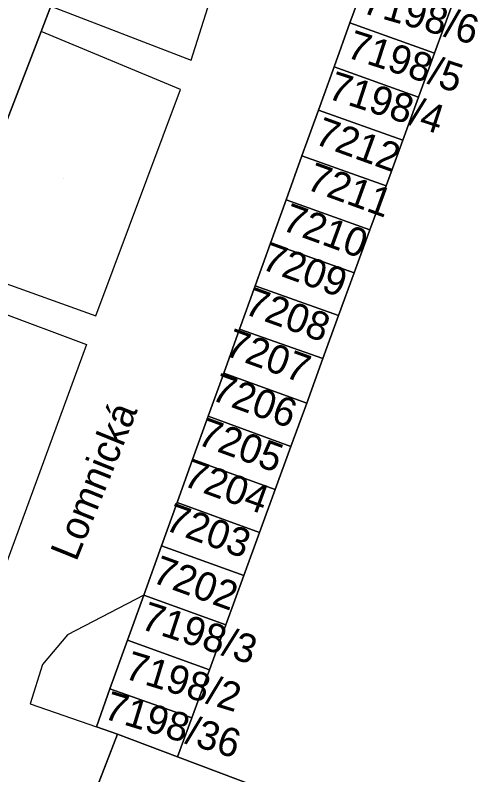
# Model space of a CAD drawing. Extents: x -266199 to -261993, y -1239047 to -1235108.
# Drawn here: x -263606.2 to -263574, y -1236545.7 to -1236492.8 of the extents above; entities that cross this region are included whole.
import ezdxf

# ---------------------------------------------------------------- set-up
doc = ezdxf.new("R2010")
doc.units = 0
for name, color, linetype in [('body_kn', 7, 'Continuous'), ('kladpar_druhypozemkov', 7, 'Continuous'), ('kladpar_hranice', 7, 'Continuous'), ('kladpar_parcelnecisla', 7, 'Continuous'), ('kladpar_plochy', 7, 'Continuous'), ('popisy', 7, 'Continuous'), ('zappar_hrandruhpozemk', 7, 'Continuous')]:
    doc.layers.add(name, color=color, linetype=linetype)

msp = doc.modelspace()

# ---------------------------------------------------------------- linework, layer by layer
at = {"layer": 'body_kn'}
for p, q in [((-263582.87, -1236493.34), (-263582.87, -1236493.34)), ((-263582.87, -1236493.34), (-263582.87, -1236493.34)), ((-263604.37, -1236493.93), (-263604.37, -1236493.93)), ((-263576.98, -1236495.45), (-263576.98, -1236495.45)), ((-263593.93, -1236495.93), (-263593.93, -1236495.93)), ((-263583.97, -1236496.4), (-263583.97, -1236496.4)), ((-263583.97, -1236496.4), (-263583.97, -1236496.4)), ((-263594.67, -1236497.98), (-263594.67, -1236497.98)), ((-263578.1, -1236498.51), (-263578.1, -1236498.51)), ((-263585.05, -1236499.41), (-263585.05, -1236499.41)), ((-263585.05, -1236499.41), (-263585.05, -1236499.41)), ((-263579.19, -1236501.51), (-263579.19, -1236501.51)), ((-263586.21, -1236502.61), (-263586.21, -1236502.61)), ((-263586.21, -1236502.61), (-263586.21, -1236502.61)), ((-263580.35, -1236504.7), (-263580.35, -1236504.7)), ((-263587.31, -1236505.67), (-263587.31, -1236505.67)), ((-263587.31, -1236505.67), (-263587.31, -1236505.67)), ((-263581.47, -1236507.75), (-263581.47, -1236507.75)), ((-263588.39, -1236508.68), (-263588.39, -1236508.68)), ((-263588.39, -1236508.68), (-263588.39, -1236508.68)), ((-263582.56, -1236510.75), (-263582.56, -1236510.75)), ((-263589.46, -1236511.65), (-263589.46, -1236511.65)), ((-263589.46, -1236511.65), (-263589.46, -1236511.65)), ((-263600.55, -1236513.75), (-263600.55, -1236513.75)), ((-263583.65, -1236513.73), (-263583.65, -1236513.73)), ((-263590.55, -1236514.67), (-263590.55, -1236514.67)), ((-263590.55, -1236514.67), (-263590.55, -1236514.67)), ((-263601.21, -1236515.75), (-263601.21, -1236515.75)), ((-263584.74, -1236516.73), (-263584.74, -1236516.73)), ((-263591.65, -1236517.73), (-263591.65, -1236517.73)), ((-263591.65, -1236517.73), (-263591.65, -1236517.73)), ((-263585.87, -1236519.82), (-263585.87, -1236519.82)), ((-263592.73, -1236520.74), (-263592.73, -1236520.74)), ((-263592.73, -1236520.74), (-263592.73, -1236520.74)), ((-263586.97, -1236522.84), (-263586.97, -1236522.84)), ((-263593.82, -1236523.75), (-263593.82, -1236523.75)), ((-263593.82, -1236523.75), (-263593.82, -1236523.75)), ((-263588.06, -1236525.84), (-263588.06, -1236525.84)), ((-263594.9, -1236526.76), (-263594.9, -1236526.76)), ((-263594.9, -1236526.76), (-263594.9, -1236526.76)), ((-263589.16, -1236528.84), (-263589.16, -1236528.84)), ((-263595.99, -1236529.78), (-263595.99, -1236529.78)), ((-263595.99, -1236529.78), (-263595.99, -1236529.78)), ((-263590.25, -1236531.84), (-263590.25, -1236531.84)), ((-263597.22, -1236533.21), (-263597.22, -1236533.21)), ((-263597.22, -1236533.21), (-263597.22, -1236533.21)), ((-263591.51, -1236535.28), (-263591.51, -1236535.28)), ((-263602.54, -1236535.98), (-263602.54, -1236535.98)), ((-263598.35, -1236536.34), (-263598.35, -1236536.34)), ((-263598.35, -1236536.34), (-263598.35, -1236536.34)), ((-263604.28, -1236538.03), (-263604.28, -1236538.03)), ((-263592.65, -1236538.41), (-263592.65, -1236538.41)), ((-263599.57, -1236539.73), (-263599.57, -1236539.73)), ((-263599.57, -1236539.73), (-263599.57, -1236539.73)), ((-263605.13, -1236540.78), (-263605.13, -1236540.78)), ((-263593.87, -1236541.75), (-263593.87, -1236541.75)), ((-263600.52, -1236542.37), (-263600.52, -1236542.37)), ((-263600.52, -1236542.37), (-263600.52, -1236542.37)), ((-263599.05, -1236542.88), (-263599.05, -1236542.88)), ((-263594.86, -1236544.47), (-263594.86, -1236544.47))]:
    msp.add_line(p, q, dxfattribs=at)
at = {"layer": 'kladpar_druhypozemkov'}
for p, q in [((-263580.36, -1236494.82), (-263580.36, -1236494.82)), ((-263581.31, -1236497.95), (-263581.31, -1236497.95)), ((-263582.16, -1236501.04), (-263582.16, -1236501.04)), ((-263602.83, -1236504.16), (-263602.83, -1236504.16)), ((-263583.18, -1236504.36), (-263583.18, -1236504.36)), ((-263584.2, -1236507.5), (-263584.2, -1236507.5)), ((-263585.41, -1236510.38), (-263585.41, -1236510.38)), ((-263586.53, -1236513.38), (-263586.53, -1236513.38)), ((-263587.69, -1236516.35), (-263587.69, -1236516.35)), ((-263588.71, -1236519.49), (-263588.71, -1236519.49)), ((-263589.78, -1236522.59), (-263589.78, -1236522.59)), ((-263590.79, -1236525.55), (-263590.79, -1236525.55)), ((-263591.96, -1236528.43), (-263591.96, -1236528.43)), ((-263593.17, -1236531.61), (-263593.17, -1236531.61)), ((-263594.71, -1236534.76), (-263594.71, -1236534.76)), ((-263595.77, -1236537.97), (-263595.77, -1236537.97)), ((-263596.93, -1236541.22), (-263596.93, -1236541.22))]:
    msp.add_line(p, q, dxfattribs=at)
at = {"layer": 'kladpar_hranice'}
for points in [[(-263631.33, -1236547.93), (-263630.37, -1236545.41), (-263629.41, -1236542.87), (-263628.45, -1236540.33), (-263627.48, -1236537.79), (-263626.49, -1236535.16), (-263620.94, -1236537.26), (-263618.12, -1236529.89), (-263617.46, -1236528.15), (-263613.87, -1236518.77), (-263611.28, -1236511.99), (-263610.57, -1236510.14), (-263606.72, -1236500.09), (-263604.37, -1236493.93), (-263603.7, -1236492.17), (-263600.8, -1236484.67), (-263611.39, -1236480.64)], [(-263617.27, -1236496.08), (-263611.39, -1236480.64), (-263600.8, -1236484.67), (-263603.7, -1236492.17), (-263604.37, -1236493.93), (-263606.72, -1236500.09)], [(-263581.67, -1236490.07), (-263582.87, -1236493.34), (-263583.97, -1236496.4), (-263585.05, -1236499.41), (-263586.21, -1236502.61), (-263587.31, -1236505.67), (-263588.39, -1236508.68), (-263589.46, -1236511.65), (-263590.55, -1236514.67), (-263591.65, -1236517.73), (-263592.73, -1236520.74), (-263593.82, -1236523.75), (-263594.9, -1236526.76), (-263595.99, -1236529.78), (-263597.22, -1236533.21), (-263598.35, -1236536.34), (-263599.57, -1236539.73)], [(-263582.87, -1236493.34), (-263581.67, -1236490.07), (-263575.73, -1236492.02), (-263576.98, -1236495.45), (-263582.87, -1236493.34)], [(-263581.95, -1236549.35), (-263594.86, -1236544.47), (-263593.87, -1236541.75), (-263592.65, -1236538.41), (-263591.51, -1236535.28), (-263590.25, -1236531.84), (-263589.16, -1236528.84), (-263588.06, -1236525.84), (-263586.97, -1236522.84), (-263585.87, -1236519.82), (-263584.74, -1236516.73), (-263583.65, -1236513.73), (-263582.56, -1236510.75), (-263581.47, -1236507.75), (-263580.35, -1236504.7), (-263579.19, -1236501.51), (-263578.1, -1236498.51), (-263576.98, -1236495.45), (-263575.73, -1236492.02)], [(-263583.97, -1236496.4), (-263582.87, -1236493.34), (-263576.98, -1236495.45), (-263578.1, -1236498.51), (-263583.97, -1236496.4)], [(-263585.05, -1236499.41), (-263583.97, -1236496.4), (-263578.1, -1236498.51), (-263579.19, -1236501.51), (-263585.05, -1236499.41)], [(-263586.21, -1236502.61), (-263585.05, -1236499.41), (-263579.19, -1236501.51), (-263580.35, -1236504.7), (-263586.21, -1236502.61)], [(-263587.31, -1236505.67), (-263586.21, -1236502.61), (-263580.35, -1236504.7), (-263581.47, -1236507.75), (-263587.31, -1236505.67)], [(-263588.39, -1236508.68), (-263587.31, -1236505.67), (-263581.47, -1236507.75), (-263582.56, -1236510.75), (-263588.39, -1236508.68)], [(-263589.46, -1236511.65), (-263588.39, -1236508.68), (-263582.56, -1236510.75), (-263583.65, -1236513.73), (-263589.46, -1236511.65)], [(-263590.55, -1236514.67), (-263589.46, -1236511.65), (-263583.65, -1236513.73), (-263584.74, -1236516.73), (-263590.55, -1236514.67)], [(-263591.65, -1236517.73), (-263590.55, -1236514.67), (-263584.74, -1236516.73), (-263585.87, -1236519.82), (-263591.65, -1236517.73)], [(-263592.73, -1236520.74), (-263591.65, -1236517.73), (-263585.87, -1236519.82), (-263586.97, -1236522.84), (-263592.73, -1236520.74)], [(-263593.82, -1236523.75), (-263592.73, -1236520.74), (-263586.97, -1236522.84), (-263588.06, -1236525.84), (-263593.82, -1236523.75)], [(-263594.9, -1236526.76), (-263593.82, -1236523.75), (-263588.06, -1236525.84), (-263589.16, -1236528.84), (-263594.9, -1236526.76)], [(-263595.99, -1236529.78), (-263594.9, -1236526.76), (-263589.16, -1236528.84), (-263590.25, -1236531.84), (-263595.99, -1236529.78)], [(-263597.22, -1236533.21), (-263595.99, -1236529.78), (-263590.25, -1236531.84), (-263591.51, -1236535.28), (-263597.22, -1236533.21)], [(-263598.35, -1236536.34), (-263597.22, -1236533.21), (-263591.51, -1236535.28), (-263592.65, -1236538.41), (-263598.35, -1236536.34)], [(-263599.57, -1236539.73), (-263598.35, -1236536.34), (-263592.65, -1236538.41), (-263593.87, -1236541.75), (-263599.57, -1236539.73)], [(-263599.57, -1236539.73), (-263600.52, -1236542.37), (-263599.05, -1236542.88), (-263604.64, -1236557.36), (-263604.49, -1236557.45), (-263605.62, -1236560.1), (-263607.48, -1236559.42), (-263610.36, -1236566.96), (-263610.97, -1236568.57), (-263613.78, -1236575.91), (-263616.59, -1236583.27), (-263617.13, -1236584.69), (-263622.68, -1236599.22), (-263623.27, -1236600.77), (-263626.16, -1236608.34)], [(-263600.52, -1236542.37), (-263599.57, -1236539.73), (-263593.87, -1236541.75), (-263594.86, -1236544.47), (-263599.05, -1236542.88), (-263600.52, -1236542.37)], [(-263605.62, -1236560.1), (-263604.49, -1236557.45), (-263604.64, -1236557.36), (-263599.05, -1236542.88), (-263594.86, -1236544.47), (-263581.95, -1236549.35), (-263587.56, -1236563.83), (-263595.86, -1236560.77), (-263596.88, -1236563.5), (-263605.62, -1236560.1)]]:
    msp.add_lwpolyline(points, dxfattribs=at)
at = {"layer": 'kladpar_plochy'}
for p, q in [((-263581.67, -1236490.07), (-263582.87, -1236493.34)), ((-263604.37, -1236493.93), (-263603.7, -1236492.17)), ((-263576.98, -1236495.45), (-263575.73, -1236492.02)), ((-263582.87, -1236493.34), (-263583.97, -1236496.4)), ((-263606.72, -1236500.09), (-263604.37, -1236493.93)), ((-263578.1, -1236498.51), (-263576.98, -1236495.45)), ((-263583.97, -1236496.4), (-263585.05, -1236499.41)), ((-263579.19, -1236501.51), (-263578.1, -1236498.51)), ((-263585.05, -1236499.41), (-263586.21, -1236502.61)), ((-263580.35, -1236504.7), (-263579.19, -1236501.51)), ((-263586.21, -1236502.61), (-263587.31, -1236505.67)), ((-263581.47, -1236507.75), (-263580.35, -1236504.7)), ((-263587.31, -1236505.67), (-263588.39, -1236508.68)), ((-263582.56, -1236510.75), (-263581.47, -1236507.75)), ((-263588.39, -1236508.68), (-263589.46, -1236511.65)), ((-263583.65, -1236513.73), (-263582.56, -1236510.75)), ((-263589.46, -1236511.65), (-263590.55, -1236514.67)), ((-263584.74, -1236516.73), (-263583.65, -1236513.73)), ((-263590.55, -1236514.67), (-263591.65, -1236517.73)), ((-263585.87, -1236519.82), (-263584.74, -1236516.73)), ((-263591.65, -1236517.73), (-263592.73, -1236520.74)), ((-263586.97, -1236522.84), (-263585.87, -1236519.82)), ((-263592.73, -1236520.74), (-263593.82, -1236523.75)), ((-263588.06, -1236525.84), (-263586.97, -1236522.84)), ((-263593.82, -1236523.75), (-263594.9, -1236526.76)), ((-263589.16, -1236528.84), (-263588.06, -1236525.84)), ((-263594.9, -1236526.76), (-263595.99, -1236529.78)), ((-263590.25, -1236531.84), (-263589.16, -1236528.84)), ((-263595.99, -1236529.78), (-263597.22, -1236533.21)), ((-263591.51, -1236535.28), (-263590.25, -1236531.84)), ((-263597.22, -1236533.21), (-263598.35, -1236536.34)), ((-263592.65, -1236538.41), (-263591.51, -1236535.28)), ((-263598.35, -1236536.34), (-263599.57, -1236539.73)), ((-263593.87, -1236541.75), (-263592.65, -1236538.41)), ((-263599.57, -1236539.73), (-263600.52, -1236542.37)), ((-263594.86, -1236544.47), (-263593.87, -1236541.75)), ((-263600.52, -1236542.37), (-263599.05, -1236542.88)), ((-263599.05, -1236542.88), (-263604.64, -1236557.36)), ((-263581.95, -1236549.35), (-263594.86, -1236544.47))]:
    msp.add_line(p, q, dxfattribs=at)
for points in [[(-263617.27, -1236496.08), (-263611.39, -1236480.64), (-263600.8, -1236484.67), (-263603.7, -1236492.17), (-263604.37, -1236493.93), (-263606.72, -1236500.09)], [(-263582.87, -1236493.34), (-263581.67, -1236490.07), (-263575.73, -1236492.02), (-263576.98, -1236495.45)], [(-263583.97, -1236496.4), (-263582.87, -1236493.34), (-263576.98, -1236495.45), (-263578.1, -1236498.51)], [(-263585.05, -1236499.41), (-263583.97, -1236496.4), (-263578.1, -1236498.51), (-263579.19, -1236501.51)], [(-263586.21, -1236502.61), (-263585.05, -1236499.41), (-263579.19, -1236501.51), (-263580.35, -1236504.7)], [(-263587.31, -1236505.67), (-263586.21, -1236502.61), (-263580.35, -1236504.7), (-263581.47, -1236507.75)], [(-263588.39, -1236508.68), (-263587.31, -1236505.67), (-263581.47, -1236507.75), (-263582.56, -1236510.75)], [(-263589.46, -1236511.65), (-263588.39, -1236508.68), (-263582.56, -1236510.75), (-263583.65, -1236513.73)], [(-263590.55, -1236514.67), (-263589.46, -1236511.65), (-263583.65, -1236513.73), (-263584.74, -1236516.73)], [(-263591.65, -1236517.73), (-263590.55, -1236514.67), (-263584.74, -1236516.73), (-263585.87, -1236519.82)], [(-263592.73, -1236520.74), (-263591.65, -1236517.73), (-263585.87, -1236519.82), (-263586.97, -1236522.84)], [(-263593.82, -1236523.75), (-263592.73, -1236520.74), (-263586.97, -1236522.84), (-263588.06, -1236525.84)], [(-263594.9, -1236526.76), (-263593.82, -1236523.75), (-263588.06, -1236525.84), (-263589.16, -1236528.84)], [(-263595.99, -1236529.78), (-263594.9, -1236526.76), (-263589.16, -1236528.84), (-263590.25, -1236531.84)], [(-263597.22, -1236533.21), (-263595.99, -1236529.78), (-263590.25, -1236531.84), (-263591.51, -1236535.28)], [(-263598.35, -1236536.34), (-263597.22, -1236533.21), (-263591.51, -1236535.28), (-263592.65, -1236538.41)], [(-263599.57, -1236539.73), (-263598.35, -1236536.34), (-263592.65, -1236538.41), (-263593.87, -1236541.75)], [(-263600.52, -1236542.37), (-263599.57, -1236539.73), (-263593.87, -1236541.75), (-263594.86, -1236544.47), (-263599.05, -1236542.88)], [(-263605.62, -1236560.1), (-263604.49, -1236557.45), (-263604.64, -1236557.36), (-263599.05, -1236542.88), (-263594.86, -1236544.47), (-263581.95, -1236549.35), (-263587.56, -1236563.83), (-263595.86, -1236560.77), (-263596.88, -1236563.5)]]:
    msp.add_lwpolyline(points, close=True, dxfattribs=at)
at = {"layer": 'zappar_hrandruhpozemk'}
for p, q in [((-263594.67, -1236497.98), (-263604.37, -1236493.93)), ((-263600.55, -1236513.75), (-263594.67, -1236497.98)), ((-263610.57, -1236510.14), (-263600.55, -1236513.75)), ((-263611.28, -1236511.99), (-263601.21, -1236515.75)), ((-263601.21, -1236515.75), (-263607, -1236531.57)), ((-263597.22, -1236533.21), (-263602.54, -1236535.98)), ((-263602.54, -1236535.98), (-263604.28, -1236538.03))]:
    msp.add_line(p, q, dxfattribs=at)
for points in [[(-263603.7, -1236492.17), (-263593.93, -1236495.93), (-263592.75, -1236492.27), (-263591.6, -1236488.03)], [(-263604.28, -1236538.03), (-263605.13, -1236540.78), (-263600.52, -1236542.37), (-263599.05, -1236542.88)]]:
    msp.add_lwpolyline(points, dxfattribs=at)

# ---------------------------------------------------------------- texts
at = {"layer": 'kladpar_parcelnecisla'}
for s, rotation, p in [('7198/6', 344, (-263582.119, -1236492.622)), ('7198/5', 342, (-263583.2, -1236495.707)), ('7198/4', 342, (-263584.507, -1236498.574)), ('7212', 340, (-263585.428, -1236501.733)), ('7211', 340, (-263586.002, -1236504.893)), ('7210', 340, (-263587.706, -1236507.732)), ('7209', 340, (-263589.131, -1236510.452)), ('7208', 340, (-263590.323, -1236513.574)), ('7207', 340, (-263591.687, -1236516.458)), ('7206', 340, (-263592.631, -1236519.562)), ('7205', 340, (-263593.593, -1236522.663)), ('7204', 340, (-263594.581, -1236525.542)), ('7203', 340, (-263595.847, -1236528.627)), ('7202', 340, (-263596.742, -1236532.272)), ('7198/3', 342, (-263597.535, -1236535.522)), ('7198/2', 343, (-263598.657, -1236538.977)), ('7198/36', 343, (-263600.107, -1236541.766))]:
    msp.add_text(s, height=2, rotation=rotation, dxfattribs=at).set_placement(p)
at = {"layer": 'popisy'}
msp.add_text('Lomnická', height=2, rotation=68, dxfattribs=at).set_placement((-263601.92, -1236530.925))

doc.saveas('drawing.dxf')
